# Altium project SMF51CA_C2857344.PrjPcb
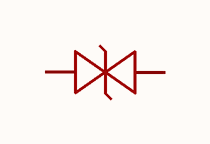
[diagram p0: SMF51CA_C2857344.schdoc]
1 sheet, 1 parts. Net scope: global (net labels, ports and power ports of the same name join across sheets).

## Sheet SMF51CA_C2857344.schdoc
size 127 x 101 mm

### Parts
D?  smf51ca_c2857344  [SMF_L2.9-W1.9-LS3.9-BI]  (value not drawn)

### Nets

Not connected (* = marked no-connect by the designer): D? 1(C) 2(A)

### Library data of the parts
D? = smf51ca_c2857344: 极性:双向;反向截止电压(Vrwm):51V;钳位电压:82.4V;峰值脉冲电流(Ipp):2.4A;峰值脉冲功率(Ppp):200W@10/1000us;击穿电压(VBR):56.7V;; Manufacturer: JSMSEMI(杰盛微); AddInBom: yes; ModelId: 9b190ad72b2a4f2384918ea07687d3cf; ModelName: DO-219AB_L2.8-W1.8-H1.0-LS3.7; ModelTransform: 145.669,70.866,0,0,0,0,0,0,0; Polarity: 双向; Reverse Stand-Off Voltage (Vrwm): 51V; Clamping Voltage: 82.4V; Peak Pulse Current (Ipp): 2.4A; Voltage - Breakdown: 56.7V; Reverse Leakage Current (Ir): 1uA; Number of Channels: 单路; Type: TVS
